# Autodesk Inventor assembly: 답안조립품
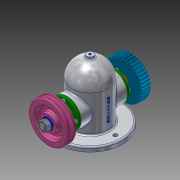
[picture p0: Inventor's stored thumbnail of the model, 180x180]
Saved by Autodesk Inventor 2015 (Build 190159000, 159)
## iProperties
Created: 2019-11
Part Number: 답안조립품
Document SubType Name: Assembly
Designer: Line503_02
Author: Line503_02
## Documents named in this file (14)
- C:\Users\Line503_02\Desktop\491104V1034\답안조립품.iam
- C:\Users\Line503_02\Desktop\491104V1034\본체.ipt
- C:\Users\Line503_02\Desktop\491104V1034\축.ipt
- C:\Users\Line503_02\Desktop\491104V1034\베어링 6203.ipt
- C:\Users\Line503_02\Desktop\491104V1034\부시.ipt
- C:\Users\Line503_02\Desktop\491104V1034\커버.ipt
- C:\Users\Line503_02\Desktop\491104V1034\오일 실 26 38 8.ipt
- C:\Users\Line503_02\Desktop\491104V1034\키 5x5x12.ipt
- C:\Users\Line503_02\Desktop\491104V1034\스퍼기어.ipt
- C:\Users\Line503_02\Desktop\491104V1034\V-벨트풀리.ipt
- V-벨트풀리.ipt
- C:\Users\Line503_02\Desktop\491104V1034\와셔 12x24.ipt
- C:\Users\Line503_02\Desktop\491104V1034\너트 M12x1.25.ipt
- C:\Users\Line503_02\Desktop\491104V1034\볼트 M4.ipt
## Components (1 placed, 1 different names)
1. V-벨트풀리:1 — 각도:3
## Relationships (1: Angle 1)
- 각도:3 [Angle]: V-벨트풀리:1
